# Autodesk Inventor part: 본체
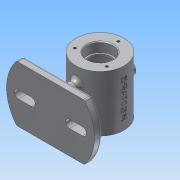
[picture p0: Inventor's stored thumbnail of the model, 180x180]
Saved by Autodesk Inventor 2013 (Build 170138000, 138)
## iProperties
Created: 2017-12
Part Number: 본체
Material: 알루미늄 6061
Document SubType Name: Modeling
Designer: Administrator
Density: 2.71 g/cm^3
Mass: 467.691 g
Surface Area: 486.469 cm^2
Volume: 172.58 cm^3
Author: Administrator
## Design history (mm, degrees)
sketch "스케치1"
  geometry: C1 r 30 at (0, 0); 1 further point
  constraints: 1 centre point, 1 coincident
  dimensions: "d0" = 60 diameter of C1
extrude "돌출1" new body sketch "스케치1" stored distance "d2" = 70; taper "d3" = 0 deg
sketch "스케치2"
  geometry: L1 (30, -35)-(-30, -35) reference; L2 (-30, -35)-(-30, 35) reference; L3 (-30, 35)-(30, 35) reference; L4 (30, 35)-(30, -35) reference; L5 (0, 35)-(0, 0); L6 (16, 35)-(16, 23); L7 (16, 23)-(14, 23); L8 (14, 23)-(14, 20); L9 (14, 20)-(25, 20); L10 (25, 20)-(25, 0); L11 (25, 0)-(0, 0); L12 (16, 35)-(0, 35); L13 (0, 0)-(0, -35)
  constraints: 18 end point, 6 parallel, 3 perpendicular, 2 midpoint, 1 point on line
  dimensions: "d4" = 50 diameter of L10 L5; "d6" = 28 diameter of L8 L5; "d8" = 32 diameter of L6 L5; "d9" = 12 distance of L6.start L6.end; "d10" = 20 distance of L9.end L10.end
revolve "회전1" sketch "스케치2" stored, may be unused: angle "d11" = 90 deg
sketch "스케치3"
  geometry: C1 r 16 at (0, 0) reference; 1 further point
  constraints: 1 vertical alignment
  dimensions: "d12" = 23 distance of C1.centre point (0, 23)
hole "구멍1" sketch "스케치3" at (0, 23) diameter "d13" = 3.242; stored, may be unused: countersink angle "d17" = 90 deg, drill point angle "d19" = 118 deg; dims "d14" = 8, "d15" = 4, "d16" = 2, "d18" = 10
node "작업 평면1"
sketch "스케치4"
  geometry: C1 r 8 at (0, 0); 1 further point
  constraints: 1 centre point, 1 coincident
  dimensions: "d24" = 16 diameter of C1
extrude "돌출2" join sketch "스케치4" stored distance "d26" = 70; taper "d27" = 0 deg
hole "구멍2" diameter "d30" = 8; stored, may be unused: countersink angle "d34" = 90 deg, drill point angle "d36" = 0 deg; dims "d28" = 10, "d29" = 10, "d31" = 8, "d32" = 4, "d33" = 2, "d35" = 10
node "작업 평면2"
sketch "스케치5"
  geometry: L1 (61.249, -35)-(42.426, -35); L2 (-61.249, -35)-(-61.249, 35); L3 (-61.249, 35)-(-42.426, 35); L4 (61.249, 35)-(61.249, -35); L5 (61.249, -35)-(-61.249, 35); L6 (-61.249, -35)-(61.249, 35); L7 (-42.426, 35)-(42.426, 35); L8 (-42.426, -35)-(-61.249, -35); L9 (42.426, -35)-(-42.426, -35); L10 (42.426, 35)-(61.249, 35); A1 r 55 centre (0, 0) between (-42.426, 35) and (-42.426, -35); 1 further point
  constraints: 20 end point, 10 parallel, 4 point on circle, 3 horizontal, 3 perpendicular, 2 midpoint, 1 centre point, 1 coincident
  dimensions: "d38" = 110 diameter of A1; "d40" = 70 distance of L2.start L2.end; "d41" = 122.49801 distance of L2.end L4.start
extrude "돌출3" join sketch "스케치5" distance "d42" = 10; taper "d43" = 0 deg
sketch "스케치6"
  geometry: L1 (-40, -5)-(-24, -5); L2 (-24, -5)-(-24, 5); L3 (-24, 5)-(-40, 5); L4 (-40, 5)-(-40, -5); A1 r 55 centre (0, 0) between (-42.426, 35) and (-42.426, -35) reference; A2 r 5 centre (-24, 0) between (-24, 5) and (-24, -5); A3 r 5 centre (-40, 0) between (-40, 5) and (-40, -5); A4 r 5 centre (-40, 0) between (-40, -5) and (-40, 5); A5 r 5 centre (-24, 0) between (-24, -5) and (-24, 5); 1 further point
  constraints: 8 end point, 8 point on circle, 4 centre point, 2 midpoint, 2 parallel, 1 coincident, 1 horizontal, 1 horizontal alignment, 1 perpendicular
  dimensions: "d47" = 16 distance of L2.end L3.end; "d49" = 10 diameter of A2; "d50" = 24 distance from line of A1.centre L2
extrude "돌출4" cut sketch "스케치6" distance "d51" = 10; taper "d52" = 0 deg
sketch "스케치7"
  geometry: L1 (-5, -15)-(5, -15); L2 (5, -15)-(5, 15); L3 (5, 15)-(-5, 15); L4 (-5, 15)-(-5, -15); L5 (-5, -15)-(5, 15); L6 (5, -15)-(-5, 15); A1 r 55 centre (0, 0) between (42.426, -35) and (42.426, 35) reference; 2 further points
  constraints: 12 end point, 4 midpoint, 2 horizontal alignment, 2 parallel, 1 horizontal, 1 perpendicular, 4 other
  dimensions: "d53" = 30 distance of L1.end L2.end; "d55" = 10 distance of L2.end L3.end
extrude "돌출5" join sketch "스케치7" stored distance "d56" = 10; taper "d57" = 0 deg
fillet "모깎기1" dims "d58" = 3
fillet "모깎기2" dims "d59" = 0.3
fillet "모깎기3" dims "d60" = 3
fillet "모깎기4" dims "d61" = 3
chamfer "모따기1" distance "d62" = 1; stored, may be unused: second distance "d63" = 2, angle "d64" = 45 deg
node "작업 평면3"
sketch "스케치8"
  geometry: 2 further points
  constraints: 1 coincident, 1 other
feature "엠보싱1" sketch "스케치8" dims "d66" = 0.5, "d67" = 0
chamfer "모따기2" distance "d68" = 1; stored, may be unused: second distance "d69" = 2, angle "d70" = 45 deg
fillet "모깎기5" dims "d71" = 5
node "솔리드1"
mirror "대칭1"
pattern_circular "원형 패턴1" dims angle "d21" = 360 deg
mirror "대칭2"
mirror "대칭3"
node "절단 모서리 투영1"
other parameters: "d23" = 37, "d37" = -62, "d65" = 154.75
